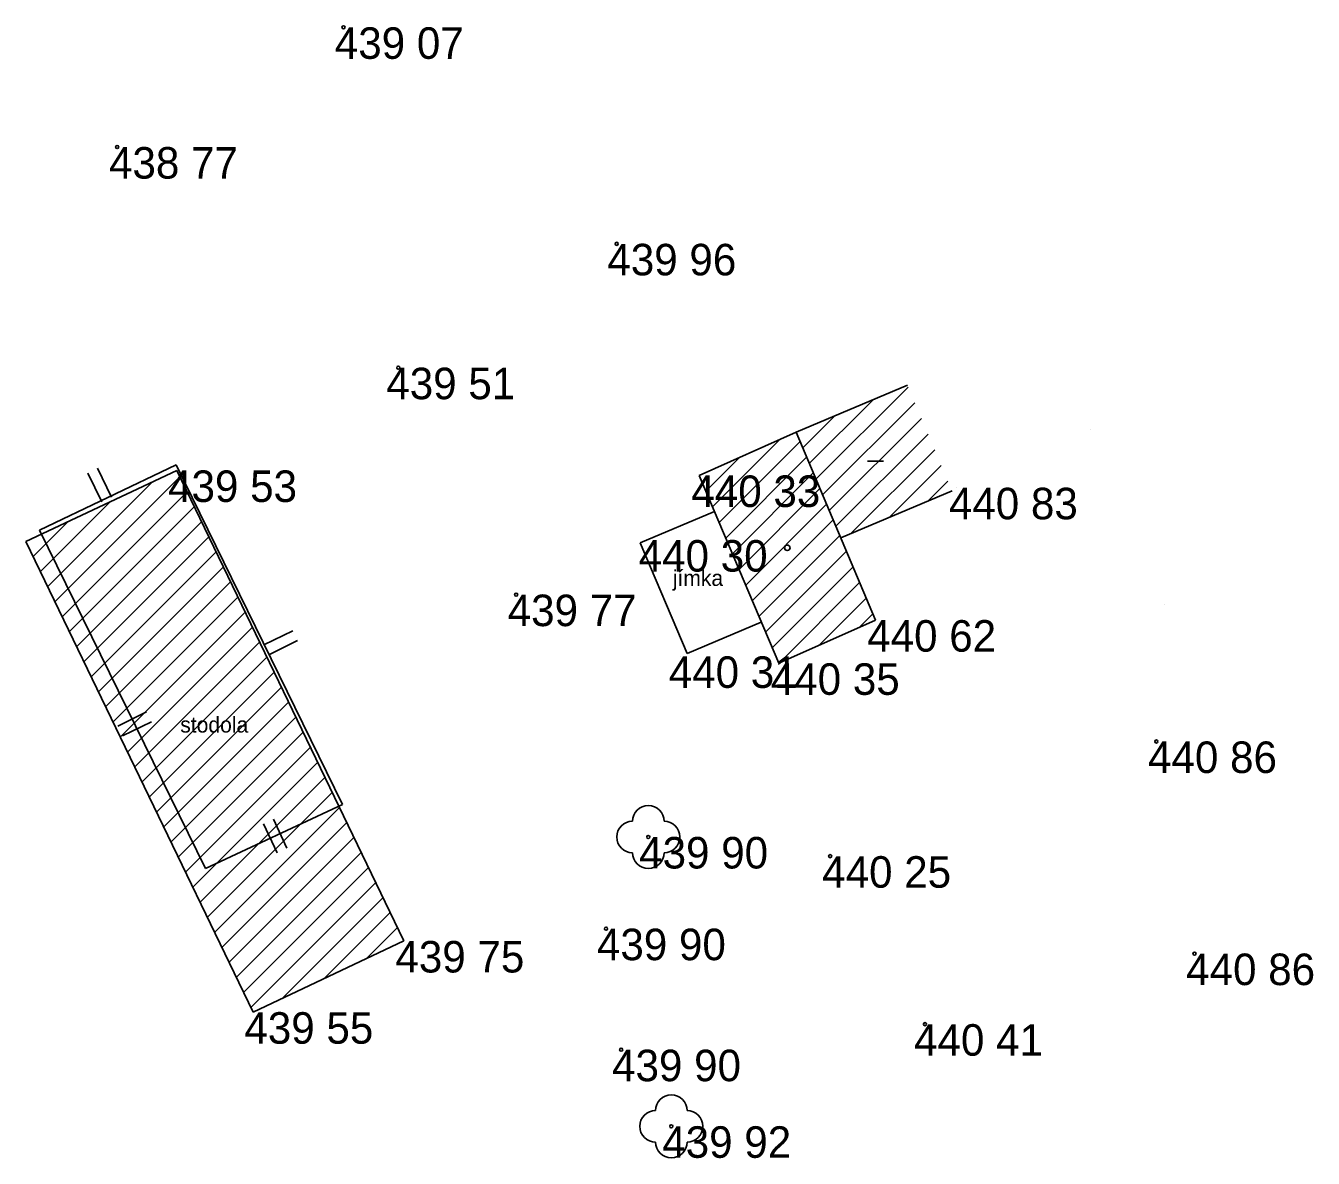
# Model space of a CAD drawing. Extents: x -554123 to -553118, y -1076825 to -1073672.
# Drawn here: x -553946.4 to -553905.55, y -1074370.91 to -1074334.98 of the extents above; entities that cross this region are included whole.
import ezdxf

# ---------------------------------------------------------------- set-up
doc = ezdxf.new("R2010")
doc.units = 0
for name, color, linetype in [('1', 7, 'Continuous'), ('14', 7, 'Continuous'), ('18', 7, 'Continuous'), ('32', 7, 'Continuous'), ('34', 7, 'Continuous'), ('47', 7, 'Continuous'), ('52', 7, 'Continuous'), ('6', 7, 'Continuous'), ('62', 7, 'Continuous')]:
    doc.layers.add(name, color=color, linetype=linetype)

# ---------------------------------------------------------------- blocks, each defined once
blk = doc.blocks.new('POINT_DISPLAY')
blk.add_line((0, 0), (0, 0))
blk = doc.blocks.new('T')
at = {"layer": '6'}
blk.add_circle((0, 0), 0.05, dxfattribs=at)
blk = doc.blocks.new('STL')
at = {"layer": '34'}
blk.add_circle((0, 0), 0.05, dxfattribs=at)
for centre, start, end in [((0, 0.5), 0, 180), ((-0.5, 0), 90, 270), ((0.5, 0), 270, 90), ((0, -0.5), 180, 0)]:
    blk.add_arc(centre, 0.5, start, end, dxfattribs=at)
blk = doc.blocks.new('ROV')
at = {"layer": '62'}
for p, q in [((-0.348, -0.51), (-0.348, 0.51)), ((0, -0.51), (0, 0.51))]:
    blk.add_line(p, q, dxfattribs=at)
blk = doc.blocks.new('BZ')
at = {"layer": '47'}
blk.add_circle((0, 0), 0.0875, dxfattribs=at)
blk = doc.blocks.new('BN')
at = {"layer": '47'}
blk.add_line((-0.25, 0), (0.25, 0), dxfattribs=at)

msp = doc.modelspace()

# ---------------------------------------------------------------- linework, layer by layer
at = {"layer": '14'}
for p, q in [((-553918.427, -1074346.387), (-553921.96, -1074347.88)), ((-553925.03, -1074349.25), (-553921.96, -1074347.88)), ((-553921.96, -1074347.88), (-553919.44, -1074353.84)), ((-553946.4, -1074351.35), (-553941.61, -1074349.09)), ((-553934.4, -1074364.02), (-553941.61, -1074349.09)), ((-553925.03, -1074349.25), (-553922.51, -1074355.21)), ((-553920.542, -1074351.233), (-553917.01, -1074349.74)), ((-553939.19, -1074366.28), (-553946.4, -1074351.35)), ((-553922.51, -1074355.21), (-553919.44, -1074353.84)), ((-553939.19, -1074366.28), (-553934.4, -1074364.02))]:
    msp.add_line(p, q, dxfattribs=at)
at = {"layer": '18'}
for p, q in [((-553924.548, -1074350.39), (-553926.902, -1074351.386)), ((-553926.902, -1074351.386), (-553925.418, -1074354.896)), ((-553923.064, -1074353.901), (-553925.418, -1074354.896))]:
    msp.add_line(p, q, dxfattribs=at)
at = {"layer": '32'}
for p, q in [((-553921.33, -1074349.371), (-553918.403, -1074346.444)), ((-553921.54, -1074348.874), (-553919.511, -1074346.845)), ((-553921.119, -1074349.868), (-553918.193, -1074346.941)), ((-553921.75, -1074348.377), (-553920.735, -1074347.362)), ((-553920.909, -1074350.365), (-553917.983, -1074347.438)), ((-553924.61, -1074350.244), (-553922.476, -1074348.11)), ((-553924.4, -1074350.741), (-553921.835, -1074348.176)), ((-553920.699, -1074350.862), (-553917.773, -1074347.935)), ((-553920.232, -1074351.102), (-553917.563, -1074348.432)), ((-553924.82, -1074349.747), (-553923.753, -1074348.68)), ((-553924.189, -1074351.238), (-553921.625, -1074348.673)), ((-553919.008, -1074350.584), (-553917.353, -1074348.929)), ((-553945.479, -1074353.257), (-553941.513, -1074349.291)), ((-553923.979, -1074351.735), (-553921.415, -1074349.17)), ((-553945.709, -1074352.781), (-553942.384, -1074349.455)), ((-553945.249, -1074353.734), (-553941.283, -1074349.768)), ((-553923.769, -1074352.232), (-553921.204, -1074349.667)), ((-553917.783, -1074350.067), (-553917.143, -1074349.426)), ((-553945.939, -1074352.304), (-553943.722, -1074350.087)), ((-553923.559, -1074352.729), (-553920.994, -1074350.164)), ((-553945.018, -1074354.211), (-553941.052, -1074350.245)), ((-553946.17, -1074351.827), (-553945.061, -1074350.718)), ((-553944.788, -1074354.688), (-553940.822, -1074350.722)), ((-553923.349, -1074353.226), (-553920.784, -1074350.661)), ((-553944.558, -1074355.165), (-553940.592, -1074351.199)), ((-553923.139, -1074353.723), (-553920.574, -1074351.158)), ((-553944.328, -1074355.642), (-553940.361, -1074351.675)), ((-553922.929, -1074354.22), (-553920.364, -1074351.655)), ((-553944.097, -1074356.118), (-553940.131, -1074352.152)), ((-553922.719, -1074354.717), (-553920.154, -1074352.152)), ((-553943.867, -1074356.595), (-553939.901, -1074352.629)), ((-553922.5, -1074355.206), (-553919.944, -1074352.649)), ((-553943.637, -1074357.072), (-553939.671, -1074353.106)), ((-553921.224, -1074354.636), (-553919.733, -1074353.146)), ((-553943.406, -1074357.549), (-553939.44, -1074353.583)), ((-553919.947, -1074354.066), (-553919.523, -1074353.643)), ((-553943.176, -1074358.026), (-553939.21, -1074354.06)), ((-553942.946, -1074358.503), (-553938.98, -1074354.536)), ((-553942.716, -1074358.979), (-553938.75, -1074355.013)), ((-553942.485, -1074359.456), (-553938.519, -1074355.49)), ((-553942.255, -1074359.933), (-553938.289, -1074355.967)), ((-553942.025, -1074360.41), (-553938.059, -1074356.444)), ((-553941.795, -1074360.887), (-553937.828, -1074356.921)), ((-553941.564, -1074361.364), (-553937.598, -1074357.397)), ((-553941.334, -1074361.84), (-553937.368, -1074357.874)), ((-553941.104, -1074362.317), (-553937.138, -1074358.351)), ((-553940.873, -1074362.794), (-553936.907, -1074358.828)), ((-553940.643, -1074363.271), (-553936.677, -1074359.305)), ((-553940.413, -1074363.748), (-553936.447, -1074359.782)), ((-553940.183, -1074364.225), (-553936.217, -1074360.258)), ((-553939.952, -1074364.701), (-553935.986, -1074360.735)), ((-553939.722, -1074365.178), (-553935.756, -1074361.212)), ((-553939.492, -1074365.655), (-553935.526, -1074361.689)), ((-553939.262, -1074366.132), (-553935.295, -1074362.166)), ((-553938.267, -1074365.845), (-553935.065, -1074362.643)), ((-553936.928, -1074365.213), (-553934.835, -1074363.119)), ((-553935.59, -1074364.581), (-553934.605, -1074363.596))]:
    msp.add_line(p, q, dxfattribs=at)
at = {"layer": '62'}
for p, q in [((-553941.63, -1074348.91), (-553945.96, -1074350.99)), ((-553936.35, -1074359.69), (-553941.63, -1074348.91)), ((-553945.96, -1074350.99), (-553940.7, -1074361.72)), ((-553940.7, -1074361.72), (-553936.35, -1074359.69))]:
    msp.add_line(p, q, dxfattribs=at)

# ---------------------------------------------------------------- block references
at = {"layer": '1'}
for p in [(-553936.32, -1074335.03), (-553943.5, -1074338.83), (-553927.65, -1074341.9), (-553934.58, -1074345.83), (-553912.63, -1074347.79), (-553941.61, -1074349.09), (-553925.03, -1074349.25), (-553916.86, -1074349.64), (-553926.7, -1074351.3), (-553930.84, -1074353.03), (-553910.27, -1074353.34), (-553919.44, -1074353.84), (-553925.64, -1074354.99), (-553922.51, -1074355.21), (-553910.53, -1074357.69), (-553926.65, -1074360.72), (-553920.88, -1074361.33), (-553927.99, -1074363.63), (-553934.4, -1074364.02), (-553909.32, -1074364.42), (-553939.19, -1074366.28), (-553917.87, -1074366.66), (-553927.51, -1074367.47), (-553925.92, -1074369.9)]:
    msp.add_blockref('POINT_DISPLAY', p, dxfattribs=at)
at = {"layer": '32'}
for p in [(-553921.96, -1074347.88), (-553925.03, -1074349.25), (-553946.4, -1074351.35)]:
    msp.add_blockref('POINT_DISPLAY', p, dxfattribs=at)
at = {"layer": '34'}
for p in [(-553926.65, -1074360.72), (-553925.92, -1074369.9)]:
    msp.add_blockref('STL', p, dxfattribs=at)
at = {"layer": '47'}
for name, p in [('BN', (-553919.441, -1074348.794)), ('BZ', (-553922.24, -1074351.544))]:
    msp.add_blockref(name, p, dxfattribs=at)
at = {"layer": '6'}
for p in [(-553936.32, -1074335.03), (-553943.5, -1074338.83), (-553927.65, -1074341.9), (-553934.58, -1074345.83), (-553930.84, -1074353.03), (-553910.53, -1074357.69), (-553920.88, -1074361.33), (-553927.99, -1074363.63), (-553909.32, -1074364.42), (-553917.87, -1074366.66), (-553927.51, -1074367.47)]:
    msp.add_blockref('T', p, dxfattribs=at)
at = {"layer": '62'}
for p, xscale, yscale, rotation in [((-553943.898, -1074349.481), 0.9999979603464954, 0.9999979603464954, 25.658189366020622), ((-553938.235, -1074354.714), 0.9999999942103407, 0.9999999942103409, -63.904473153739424), ((-553942.871, -1074357.291), 0.9999993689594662, 0.9999993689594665, -63.88514318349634), ((-553938.329, -1074360.613), 1.0000003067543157, 1.0000003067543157, 25.016941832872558)]:
    msp.add_blockref('ROV', p, dxfattribs=dict(at, xscale=xscale, yscale=yscale, rotation=rotation))

# ---------------------------------------------------------------- texts
at = {"layer": '52'}
for s, p in [('jímka', (-553925.872, -1074352.754)), ('stodola', (-553941.498, -1074357.407))]:
    msp.add_text(s, height=0.5, dxfattribs=at).set_placement(p)
at = {"layer": '6'}
for s, p in [('439 07 ', (-553936.594, -1074336.03)), ('438 77 ', (-553943.758, -1074339.83)), ('439 96 ', (-553927.948, -1074342.9)), ('439 51 ', (-553934.961, -1074346.83)), ('439 53 ', (-553941.884, -1074350.09)), ('440 33 ', (-553925.282, -1074350.25)), ('440 83 ', (-553917.112, -1074350.64)), ('440 30 ', (-553926.954, -1074352.3)), ('439 77 ', (-553931.11, -1074354.03)), ('440 62 ', (-553919.704, -1074354.84)), ('440 31 ', (-553925.999, -1074355.99)), ('440 35 ', (-553922.762, -1074356.21)), ('440 86 ', (-553910.794, -1074358.69)), ('439 90 ', (-553926.938, -1074361.72)), ('440 25 ', (-553921.132, -1074362.33)), ('439 90 ', (-553928.278, -1074364.63)), ('439 75 ', (-553934.672, -1074365.02)), ('440 86 ', (-553909.584, -1074365.42)), ('439 55 ', (-553939.464, -1074367.28)), ('440 41 ', (-553918.217, -1074367.66)), ('439 90 ', (-553927.798, -1074368.47)), ('439 92 ', (-553926.206, -1074370.9))]:
    msp.add_text(s, height=1, dxfattribs=at).set_placement(p)

doc.saveas('drawing.dxf')
